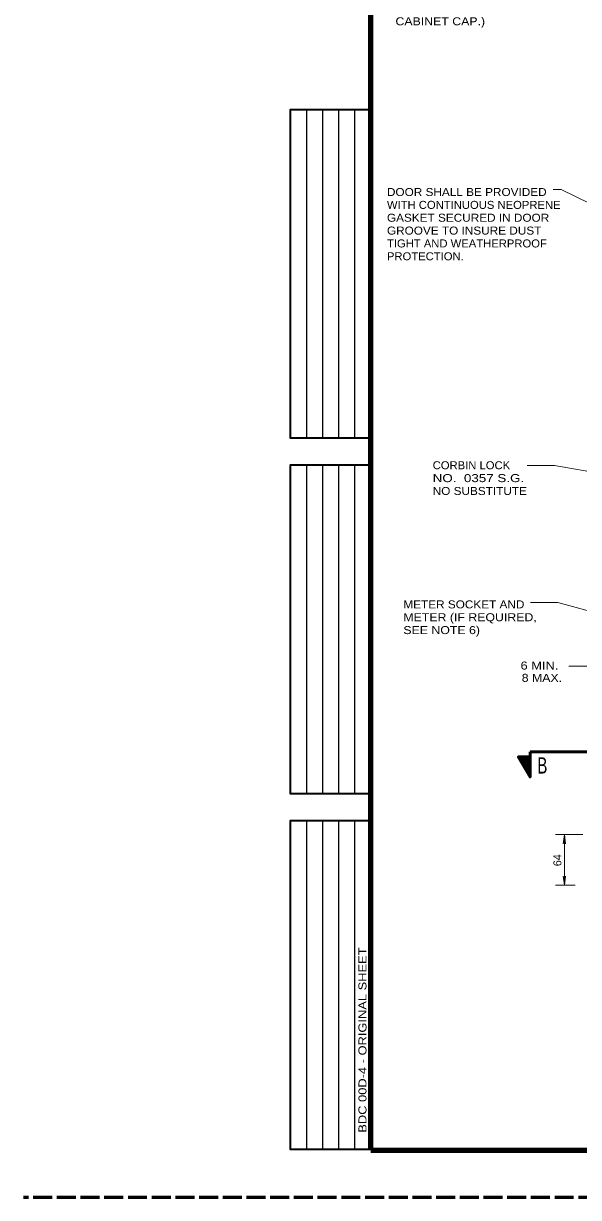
# Model space of a CAD drawing. Extents: x 312583 to 312853, y 144419 to 144586.
# Drawn here: x 312583.5 to 312636.2, y 144418.6 to 144530 of the extents above; entities that cross this region are included whole.
import ezdxf
from ezdxf.enums import TextEntityAlignment as Align

# ---------------------------------------------------------------- set-up
doc = ezdxf.new("R2010")
doc.units = 0
doc.header["$LTSCALE"] = 0.3
doc.linetypes.add('LONG_DASHED', pattern=[7.5, 6, -1.5])
for name, color, linetype, lineweight in [('1', 7, 'Continuous', 40), ('2', 7, 'Continuous', 13), ('63', 7, 'LONG_DASHED', 60)]:
    doc.layers.add(name, color=color, linetype=linetype, lineweight=lineweight)

msp = doc.modelspace()

# ---------------------------------------------------------------- linework, layer by layer
at = {"layer": '1', "lineweight": 25}
for p, q in [((312610.4087, 144490.6573), (312610.4087, 144521.8756)), ((312611.9315, 144490.6573), (312611.9315, 144521.8756)), ((312613.4543, 144490.6573), (312613.4543, 144521.8756)), ((312614.9772, 144490.6573), (312614.9772, 144521.8756)), ((312610.4087, 144456.901), (312610.4087, 144488.1192)), ((312611.9315, 144456.901), (312611.9315, 144488.1192)), ((312613.4543, 144456.901), (312613.4543, 144488.1192)), ((312614.9772, 144456.901), (312614.9772, 144488.1192)), ((312610.4087, 144423.1446), (312610.4087, 144454.3629)), ((312611.9315, 144423.1446), (312611.9315, 144454.3629)), ((312613.4543, 144423.1446), (312613.4543, 144454.3629)), ((312614.9772, 144423.1446), (312614.9772, 144454.3629))]:
    msp.add_line(p, q, dxfattribs=at)
at = {"layer": '1', "lineweight": 53}
for p in [(312648.1983, 144460.8876), (312631.6076, 144460.4123)]:
    msp.add_line(p, (312631.6076, 144460.8876), dxfattribs=at)
at = {"layer": '1', "lineweight": 35}
for p, q in [((312630.5266, 144460.4123), (312630.5113, 144460.3969)), ((312630.5726, 144460.4123), (312630.5189, 144460.3739)), ((312630.6263, 144460.4123), (312630.5343, 144460.3586)), ((312630.6723, 144460.4123), (312630.5496, 144460.3356)), ((312630.7259, 144460.4123), (312630.5573, 144460.3126)), ((312630.7643, 144460.4123), (312630.5726, 144460.2973)), ((312630.8179, 144460.4123), (312630.5803, 144460.2743)), ((312630.8639, 144460.4123), (312630.5956, 144460.2513)), ((312630.9099, 144460.4123), (312630.6033, 144460.2359)), ((312630.9559, 144460.4123), (312630.6186, 144460.2053)), ((312631.0096, 144460.4123), (312630.6263, 144460.1899)), ((312631.0556, 144460.4123), (312630.6416, 144460.1669)), ((312631.1016, 144460.4123), (312630.6493, 144460.1439)), ((312631.1553, 144460.4123), (312630.6646, 144460.1286)), ((312631.2013, 144460.4123), (312630.6723, 144460.1056)), ((312631.2473, 144460.4123), (312630.6876, 144460.0903)), ((312631.3009, 144460.4123), (312630.7029, 144460.0673)), ((312631.3469, 144460.4123), (312630.7106, 144460.0443)), ((312631.3929, 144460.4123), (312630.7259, 144460.0289)), ((312631.4389, 144460.4123), (312630.7413, 144460.0059)), ((312631.4926, 144460.4123), (312630.7489, 144459.9829)), ((312631.5309, 144460.4123), (312630.7643, 144459.9676)), ((312631.5846, 144460.4123), (312630.7719, 144459.9369)), ((312631.6076, 144460.3969), (312630.7873, 144459.9216)), ((312631.6076, 144460.3663), (312630.7949, 144459.8986)), ((312631.6076, 144460.3356), (312630.8103, 144459.8756)), ((312631.6076, 144460.3126), (312630.8179, 144459.8603)), ((312631.6076, 144460.2819), (312630.8333, 144459.8373)), ((312631.5999, 144460.2589), (312630.8409, 144459.8143)), ((312631.5999, 144460.2283), (312630.8563, 144459.7989)), ((312631.6076, 144460.2053), (312630.8639, 144459.7759)), ((312631.6076, 144460.1746), (312630.8793, 144459.7529)), ((312631.6076, 144460.1439), (312630.8946, 144459.7376)), ((312631.6076, 144460.1209), (312630.9023, 144459.7146)), ((312631.6076, 144460.0903), (312630.9176, 144459.6916)), ((312631.6076, 144460.0596), (312630.9329, 144459.6686)), ((312631.6076, 144460.0366), (312630.9406, 144459.6533)), ((312631.5999, 144460.0059), (312630.9559, 144459.6303)), ((312631.6076, 144459.9753), (312630.9636, 144459.6073)), ((312631.6076, 144459.9523), (312630.9789, 144459.5919)), ((312631.6076, 144459.9293), (312630.9866, 144459.5689)), ((312631.6076, 144459.8986), (312631.0019, 144459.5459)), ((312631.6076, 144459.8679), (312631.0096, 144459.5306)), ((312631.6076, 144459.8373), (312631.0249, 144459.5076)), ((312631.6076, 144459.8143), (312631.0326, 144459.4846)), ((312631.6076, 144459.7836), (312631.0479, 144459.4693)), ((312631.5999, 144459.7606), (312631.0556, 144459.4386)), ((312631.6076, 144459.7299), (312631.0709, 144459.4233)), ((312631.6076, 144459.7069), (312631.0863, 144459.4003)), ((312631.6076, 144459.6763), (312631.0939, 144459.3773)), ((312631.6076, 144459.6456), (312631.1093, 144459.3619)), ((312631.6076, 144459.6226), (312631.1169, 144459.3389)), ((312631.6076, 144459.5919), (312631.1323, 144459.3159)), ((312631.6076, 144459.5613), (312631.1399, 144459.3006)), ((312631.6076, 144459.5383), (312631.1553, 144459.2776)), ((312631.6076, 144459.5076), (312631.1629, 144459.2546)), ((312631.6076, 144459.4769), (312631.1783, 144459.2393)), ((312631.6076, 144459.4539), (312631.1859, 144459.2163)), ((312631.6076, 144459.4309), (312631.2013, 144459.1933)), ((312631.6076, 144459.4003), (312631.2089, 144459.1703)), ((312631.6076, 144459.3696), (312631.2243, 144459.1549)), ((312631.6076, 144459.3389), (312631.2396, 144459.1319)), ((312631.6076, 144459.3159), (312631.2473, 144459.1089)), ((312631.6076, 144459.2853), (312631.2626, 144459.0936)), ((312631.6076, 144459.2623), (312631.2779, 144459.0706)), ((312631.6076, 144459.2316), (312631.2856, 144459.0476)), ((312631.6076, 144459.2086), (312631.3009, 144459.0323)), ((312631.6076, 144459.1779), (312631.3086, 144459.0093)), ((312631.6076, 144459.1473), (312631.3239, 144458.9863)), ((312631.6076, 144459.1243), (312631.3316, 144458.9709)), ((312631.6076, 144459.0936), (312631.3469, 144458.9403)), ((312631.6076, 144459.0706), (312631.3546, 144458.9249)), ((312631.6076, 144459.0399), (312631.3699, 144458.9019)), ((312631.6076, 144459.0093), (312631.3776, 144458.8789)), ((312631.6076, 144458.9863), (312631.3929, 144458.8636)), ((312631.6076, 144458.9556), (312631.4006, 144458.8406)), ((312631.6076, 144458.9326), (312631.4159, 144458.8176)), ((312631.6076, 144458.9019), (312631.4313, 144458.8023)), ((312631.6076, 144458.8713), (312631.4389, 144458.7793)), ((312631.6076, 144458.8406), (312631.4543, 144458.7563)), ((312631.6076, 144458.8176), (312631.4696, 144458.7409)), ((312631.6076, 144458.7869), (312631.4773, 144458.7179)), ((312631.6076, 144458.7639), (312631.4926, 144458.6949)), ((312631.6076, 144458.7409), (312631.5003, 144458.6719)), ((312631.6076, 144458.7103), (312631.5156, 144458.6566)), ((312631.6076, 144458.6796), (312631.5233, 144458.6336)), ((312631.6076, 144458.6489), (312631.5386, 144458.6106)), ((312631.6076, 144458.6259), (312631.5463, 144458.5953)), ((312631.6076, 144458.5953), (312631.5616, 144458.5723)), ((312631.6076, 144458.5723), (312631.5693, 144458.5493)), ((312631.6076, 144458.5416), (312631.5846, 144458.5339)), ((312631.6076, 144458.5109), (312631.5923, 144458.5109))]:
    msp.add_line(p, q, dxfattribs=at)
at = {"layer": '1', "lineweight": 158}
msp.add_line((312616.5, 144423.0846), (312849, 144423.0846), dxfattribs=at)
msp.add_lwpolyline([(312616.5, 144423.1446), (312616.5, 144585.0846), (312849, 144585.0846)], dxfattribs=at)
at = {"layer": '1', "lineweight": 35}
for points in [[(312616.5, 144490.6573), (312608.8858, 144490.6573), (312608.8858, 144521.8756), (312616.5, 144521.8756)], [(312616.5, 144456.901), (312608.8858, 144456.901), (312608.8858, 144488.1192), (312616.5, 144488.1192)], [(312616.5, 144423.1446), (312608.8858, 144423.1446), (312608.8858, 144454.3629), (312616.5, 144454.3629)]]:
    msp.add_lwpolyline(points, dxfattribs=at)
at = {"layer": '1', "lineweight": 53}
msp.add_lwpolyline([(312631.6076, 144460.4123), (312630.4959, 144460.4123), (312631.6076, 144458.4956)], close=True, dxfattribs=at)
at = {"layer": '2'}
for p, q in [((312634.5516, 144514.2706), (312633.8017, 144514.2706)), ((312640.3859, 144511.4033), (312634.5516, 144514.2706)), ((312633.9306, 144488.0583), (312631.3239, 144488.0583)), ((312641.4976, 144486.7626), (312633.9306, 144488.0583)), ((312634.2373, 144475.0556), (312631.6383, 144475.0556)), ((312645.0549, 144472.1423), (312634.2373, 144475.0556)), ((312635.2799, 144469.0219), (312637.3883, 144469.0219)), ((312636.6293, 144453.0293), (312634.0303, 144453.0293)), ((312634.8659, 144453.0293), (312634.7586, 144452.1629)), ((312634.8659, 144448.2376), (312634.8659, 144453.0293)), ((312634.8659, 144453.0293), (312634.9733, 144452.1629)), ((312634.7586, 144452.1629), (312634.8659, 144452.4389)), ((312634.9733, 144452.1629), (312634.8659, 144452.4389)), ((312634.7586, 144449.1039), (312634.8659, 144448.8279)), ((312634.8659, 144448.2376), (312634.7586, 144449.1039)), ((312634.9733, 144449.1039), (312634.8659, 144448.8279)), ((312634.8659, 144448.2376), (312634.9733, 144449.1039)), ((312635.9009, 144448.2376), (312634.0303, 144448.2376))]:
    msp.add_line(p, q, dxfattribs=at)
at = {"layer": '63'}
msp.add_line((312851.75, 144418.5846), (312583.526, 144418.5846), dxfattribs=at)

# ---------------------------------------------------------------- texts
at = {"layer": '1', "width": 0.7}
msp.add_text('B', height=1.533, dxfattribs=at).set_placement((312632.7768, 144458.8329), align=Align.CENTER)
at = {"layer": '1', "width": 1.2}
msp.add_text('BDC 00D-4 - ORIGINAL SHEET', height=0.7614, rotation=90, dxfattribs=at).set_placement((312616.0832, 144424.7374))
at = {"layer": '2'}
for s, width, p in [('CABINET CAP.)', 1.15, (312618.8347, 144529.8539)), ('DOOR SHALL BE PROVIDED', 1.1, (312618.0276, 144513.6486)), ('WITH CONTINUOUS NEOPRENE', 1.05, (312618.0276, 144512.4286)), ('GASKET SECURED IN DOOR', 1.1, (312618.0276, 144511.2086)), ('GROOVE TO INSURE DUST', 1.1, (312618.0276, 144509.9886)), ('TIGHT AND WEATHERPROOF', 1.05, (312618.0276, 144508.7686)), ('PROTECTION.', 1.05, (312618.0276, 144507.5486)), ('CORBIN LOCK', 1.05, (312622.3693, 144487.7123)), ('NO.  0357 S.G.', 1.25, (312622.3693, 144486.4923)), ('NO SUBSTITUTE', 1.1, (312622.3693, 144485.2723)), ('METER SOCKET AND', 1.1, (312619.5849, 144474.5065)), ('METER (IF REQUIRED,', 1.15, (312619.5849, 144473.2865)), ('SEE NOTE 6)', 1.15, (312619.5849, 144472.0665)), ('6 MIN.', 1.2, (312630.7076, 144468.699)), ('8 MAX.', 1.15, (312630.8198, 144467.5317))]:
    msp.add_text(s, height=0.76, dxfattribs=dict(at, width=width)).set_placement(p)
msp.add_text('64', height=0.76, rotation=90, dxfattribs=at).set_placement((312634.5812, 144450.0373))

doc.saveas('drawing.dxf')
